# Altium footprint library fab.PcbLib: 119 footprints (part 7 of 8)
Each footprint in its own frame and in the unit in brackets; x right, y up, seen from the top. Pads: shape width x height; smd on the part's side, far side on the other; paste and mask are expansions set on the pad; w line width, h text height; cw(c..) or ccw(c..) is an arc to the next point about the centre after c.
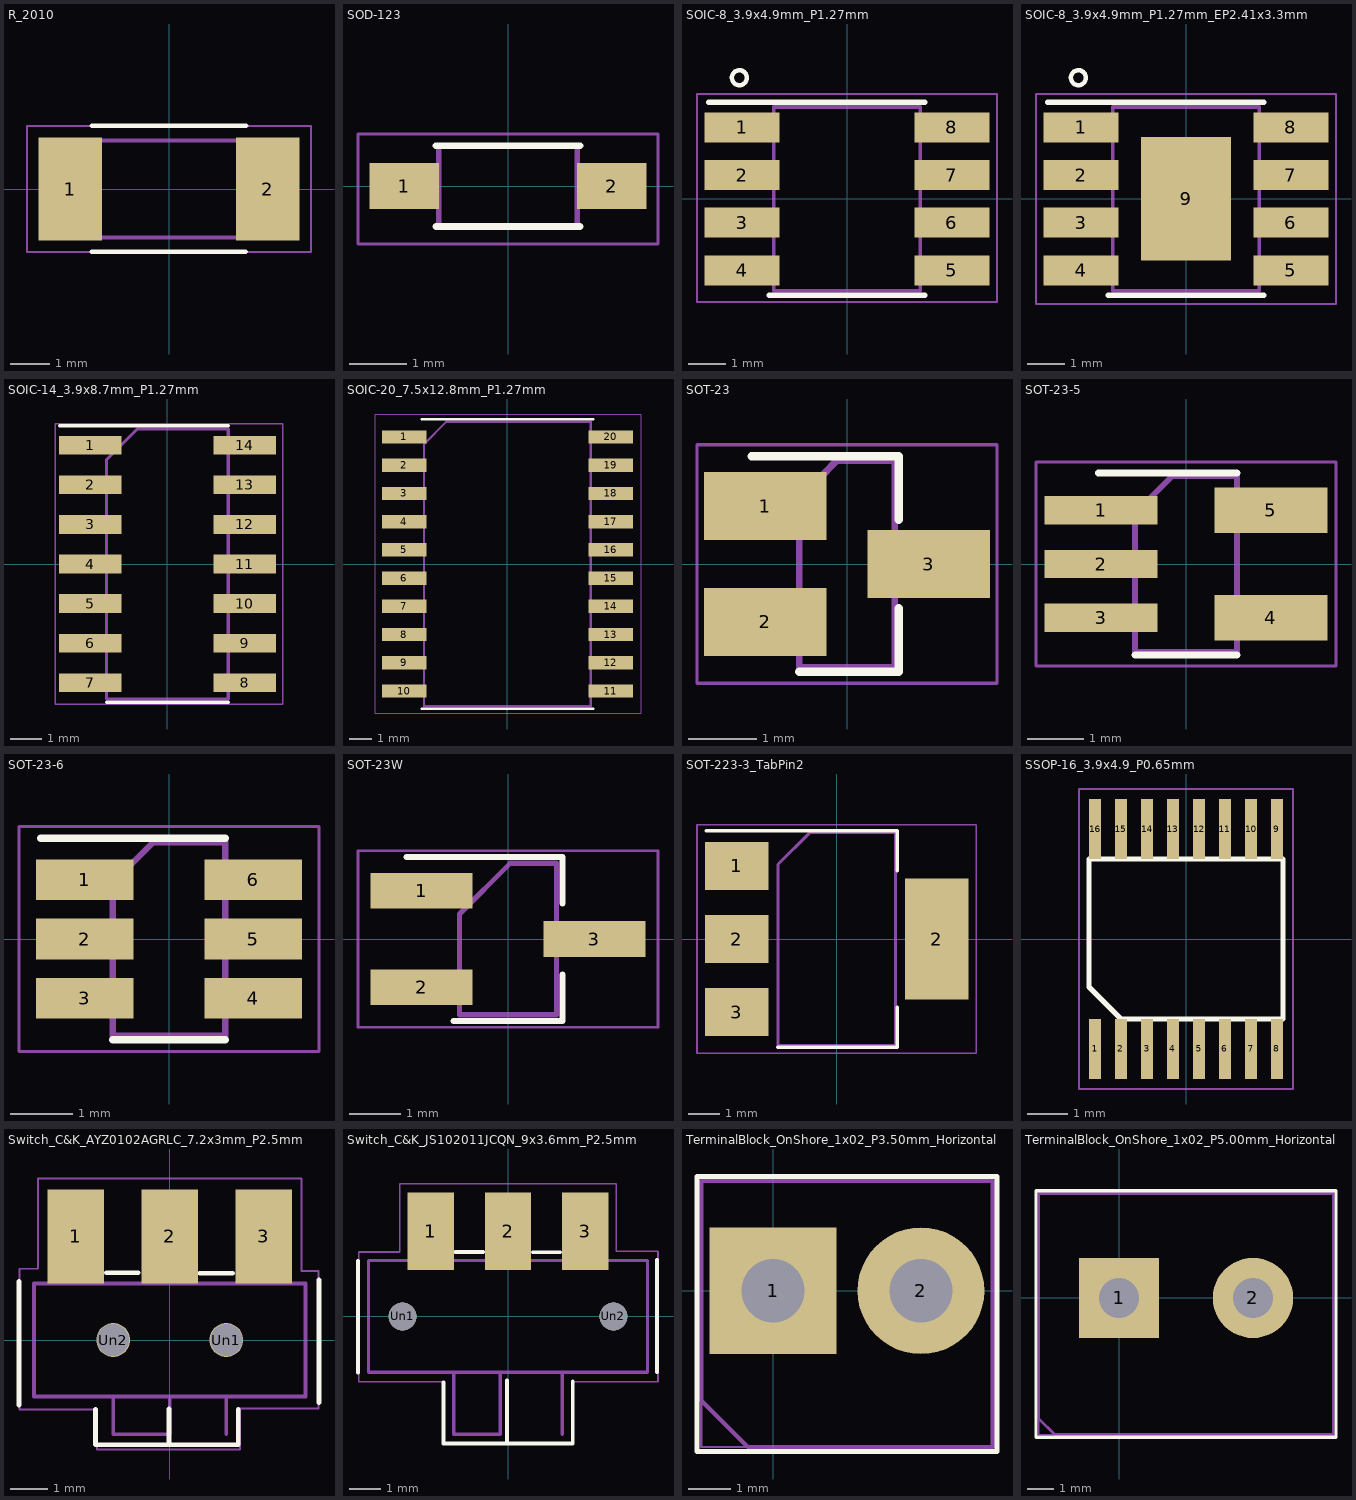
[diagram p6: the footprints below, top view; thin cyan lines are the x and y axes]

## R_2010 [mm]
pads (2):
  rect 1.6x2.6 smd: 1(-2.5,0) 2(2.5,0)
F.SilkS:
  lines w0.12: -1.96,-1.59 1.94,-1.59 ; -1.95,1.6 1.95,1.6
F.CrtYd:
  lines w0.05: -3.6,-1.6 3.6,-1.6 3.6,1.6 -3.6,1.6 -3.6,-1.6
F.Fab:
  lines w0.1: -2.5,-1.225 2.5,-1.225 2.5,1.225 -2.5,1.225 -2.5,-1.225
  text "%R" at -0.393,-0.294 h1

## SOD-123 [mm]
pads (2):
  rect 1.2x0.8 smd: 1(-1.8,0) 2(1.8,0)
F.SilkS:
  lines w0.12: -1.25,-0.7 1.25,-0.7 ; -1.25,0.7 1.25,0.7
B.CrtYd:
  lines w0.05: -2.6,-1 2.6,-1 2.6,0.9 -2.6,0.9 -2.6,-1
F.Fab:
  lines w0.1: -1.2,-0.7 1.2,-0.7 1.2,0.7 -1.2,0.7 -1.2,-0.7

## SOIC-8_3.9x4.9mm_P1.27mm [mm]
pads (8):
  rect 2x0.8 smd: 1(-2.8,1.905) 2(-2.8,0.635) 3(-2.8,-0.635) 4(-2.8,-1.905) 5(2.8,-1.905) 6(2.8,-0.635) 7(2.8,0.635) 8(2.8,1.905)
F.SilkS:
  circle w0.12: c-2.87,3.23 r0.2
  lines w0.15: -3.69,2.575 2.075,2.575 ; -2.075,-2.575 2.075,-2.575
B.CrtYd:
  lines w0.05: -4,-2.75 4,-2.75 4,2.8 -4,2.8 -4,-2.75
F.Fab:
  lines w0.1: -1.95,-2.45 1.95,-2.45 1.95,2.45 -1.95,2.45 -1.95,-2.45
  text "%R" at -0.353,-0.264 h0.9

## SOIC-8_3.9x4.9mm_P1.27mm_EP2.41x3.3mm [mm]
pads (9):
  rect 2x0.8 smd: 1(-2.8,1.905) 2(-2.8,0.635) 3(-2.8,-0.635) 4(-2.8,-1.905) 5(2.8,-1.905) 6(2.8,-0.635) 7(2.8,0.635) 8(2.8,1.905)
  rect 2.41x3.3 smd: 9(0,0)
F.SilkS:
  circle w0.12: c-2.87,3.23 r0.2
  lines w0.15: -3.69,2.575 2.075,2.575 ; -2.075,-2.575 2.075,-2.575
B.CrtYd:
  lines w0.05: -4,-2.8 -4,2.8 4,2.8 4,-2.8 -4,-2.8
F.Fab:
  lines w0.1: -1.95,-2.45 -1.95,2.45 1.95,2.45 1.95,-2.45 -1.95,-2.45
  text "%R" at -0.353,-0.264 h0.9

## SOIC-14_3.9x8.7mm_P1.27mm [mm]
pads (14):
  rect 2x0.6 smd: 1(-2.475,3.81) 2(-2.475,2.54) 3(-2.475,1.27) 4(-2.475,0) 5(-2.475,-1.27) 6(-2.475,-2.54) 7(-2.475,-3.81) 8(2.475,-3.81) 9(2.475,-2.54) 10(2.475,-1.27) 11(2.475,0) 12(2.475,1.27) 13(2.475,2.54) 14(2.475,3.81)
F.SilkS:
  lines w0.12: -3.45,4.435 0,4.435 1.95,4.435 ; -1.95,-4.435 0,-4.435 1.95,-4.435
F.CrtYd:
  lines w0.05: -3.6,-4.5 3.7,-4.5 3.7,4.5 -3.6,4.5 -3.6,-4.5
  text "%R" at -0.393,-0.294 h1
F.Fab:
  lines w0.1: -1.95,-4.325 -1.95,3.35 -0.975,4.325 1.95,4.325 1.95,-4.325 -1.95,-4.325

## SOIC-20_7.5x12.8mm_P1.27mm [mm]
pads (20):
  rect 2x0.6 smd: 1(-4.65,5.715) 2(-4.65,4.445) 3(-4.65,3.175) 4(-4.65,1.905) 5(-4.65,0.635) 6(-4.65,-0.635) 7(-4.65,-1.905) 8(-4.65,-3.175) 9(-4.65,-4.445) 10(-4.65,-5.715) 11(4.65,-5.715) 12(4.65,-4.445) 13(4.65,-3.175) 14(4.65,-1.905) 15(4.65,-0.635) 16(4.65,0.635) 17(4.65,1.905) 18(4.65,3.175) 19(4.65,4.445) 20(4.65,5.715)
F.SilkS:
  lines w0.12: -3.86,-6.51 0,-6.51 3.86,-6.51 ; -3.86,6.51 0,6.51 3.86,6.51
B.CrtYd:
  lines w0.05: -5.95,-6.75 -5.95,6.75 6,6.75 6,-6.75 -5.95,-6.75
  text "%R" at -0.393,-0.294 h1
F.Fab:
  lines w0.1: -3.75,-6.4 3.75,-6.4 3.75,6.4 -2.75,6.4 -3.75,5.4 -3.75,-6.4

## SOT-23 [mm]
pads (3):
  rect 1.8x1 smd: 1(-1.2,0.85) 2(-1.2,-0.85) 3(1.2,0)
F.SilkS:
  lines w0.12: -1.4,1.58 0.76,1.58 0.76,0.65 ; -0.7,-1.58 0.76,-1.58 0.76,-0.65
F.CrtYd:
  lines w0.05: -2.2,-1.75 2.2,-1.75 2.2,1.75 -2.2,1.75 -2.2,-1.75
F.Fab:
  lines w0.1: -0.7,-1.52 0.7,-1.52 0.7,1.52 -0.15,1.52 -0.7,0.95 -0.7,-1.5
  text "%R" at 0.147,-0.197 h0.5

## SOT-23-5 [mm]
pads (5):
  rect 2x0.5 smd: 1(-1.5,0.95) 2(-1.5,0) 3(-1.5,-0.95)
  rect 2x0.8 smd: 4(1.5,-0.95) 5(1.5,0.95)
F.SilkS:
  lines w0.12: -1.55,1.61 0.9,1.61 ; -0.9,-1.61 0.9,-1.61
F.CrtYd:
  lines w0.05: -2.65,-1.8 -2.65,1.8 2.65,1.8 2.65,-1.8 -2.65,-1.8
F.Fab:
  lines w0.1: -0.9,-1.55 -0.9,0.9 -0.25,1.55 0.9,1.55 0.9,-1.55 -0.9,-1.55
  text "%R" at 0.147,-0.197 h0.5

## SOT-23-6 [mm]
pads (6):
  rect 1.56x0.65 smd: 1(-1.35,0.95) 2(-1.35,0) 3(-1.35,-0.95) 4(1.35,-0.95) 5(1.35,0) 6(1.35,0.95)
F.SilkS:
  lines w0.12: -2.05,1.61 0.9,1.61 ; -0.9,-1.61 0.9,-1.61
F.CrtYd:
  lines w0.05: -2.4,-1.8 2.4,-1.8 2.4,1.8 -2.4,1.8 -2.4,-1.8
F.Fab:
  lines w0.1: -0.9,-1.55 0.9,-1.55 0.9,1.55 -0.25,1.55 -0.9,0.9 -0.9,-1.55
  text "%R" at 0.147,-0.197 h0.5

## SOT-23W [mm]
pads (3):
  rect 2x0.7 smd: 1(-1.7,0.95) 2(-1.7,-0.95) 3(1.7,0)
F.SilkS:
  lines w0.12: -2,1.61 1.075,1.61 ; -1.075,-1.61 1.075,-1.61 1.075,-0.7 ; 1.075,0.7 1.075,1.6
F.CrtYd:
  lines w0.05: -2.95,-1.74 2.95,-1.74 2.95,1.74 -2.95,1.74 -2.95,-1.74
F.Fab:
  lines w0.1: -0.955,-1.49 -0.955,0.49 0.045,1.49 0.955,1.49 0.955,-1.49 -0.955,-1.49
  text "%R" at 0.147,-0.197 h0.5

## SOT-223-3_TabPin2 [mm]
pads (4):
  rect 2x1.5 smd: 1(-3.15,2.3) 2(-3.15,0) 3(-3.15,-2.3)
  rect 2x3.8 smd: 2(3.15,0)
F.SilkS:
  lines w0.12: -4.1,3.41 1.91,3.41 1.91,2.15 ; -1.85,-3.41 1.91,-3.41 1.91,-2.15
F.CrtYd:
  lines w0.05: -4.4,-3.6 4.4,-3.6 4.4,3.6 -4.4,3.6 -4.4,-3.6
F.Fab:
  lines w0.1: -1.85,-3.35 -1.85,2.35 -0.85,3.35 1.85,3.35 1.85,-3.35 -1.85,-3.35
  text "%R" at 0.234,-0.313 h0.8

## SSOP-16_3.9x4.9_P0.65mm [mm]
pads (16):
  rect 0.3x1.5 smd: 1(-2.275,-2.75) 2(-1.625,-2.75) 3(-0.975,-2.75) 4(-0.325,-2.75) 5(0.325,-2.75) 6(0.975,-2.75) 7(1.625,-2.75) 8(2.275,-2.75) 9(2.275,2.75) 10(1.625,2.75) 11(0.975,2.75) 12(0.325,2.75) 13(-0.325,2.75) 14(-0.975,2.75) 15(-1.625,2.75) 16(-2.275,2.75)
F.SilkS:
  lines w0.12: -2.425,-1.2 -1.625,-2 2.425,-2 2.425,2 -2.425,2 -2.425,-1.2
F.CrtYd:
  lines w0.05: -2.68,-3.75 2.68,-3.75 2.68,3.75 -2.68,3.75 -2.68,-3.75

## Switch_C&K_AYZ0102AGRLC_7.2x3mm_P2.5mm [mm]
pads (5):
  rect 1.5x2.5 smd: 1(-2.5,2.75) 2(0,2.75) 3(2.5,2.75)
  round 0.9 hole 0.85: Un1(1.5,0) Un2(-1.5,0)
F.SilkS:
  lines w0.12: -4,-1.73 -4,1.56 ; -1.97,-1.84 -1.97,-2.78 1.82,-2.78 1.82,-1.84 ; -1.68,1.78 -0.83,1.78 ; -0.02,-2.77 -0.02,-1.82 ; 0.8,1.77 1.67,1.77 ; 3.96,-1.67 3.96,1.6
F.CrtYd:
  lines w0.05: -3.99,-1.84 -1.93,-1.84 -1.93,-2.91 1.86,-2.91 1.86,-1.82 3.95,-1.82 3.95,1.83 3.5,1.83 3.5,4.29 -3.5,4.29 -3.5,1.89 -3.99,1.89 -3.99,-1.84
F.Fab:
  lines w0.1: -1.5,-1.5 -1.5,-2.5 0,-2.5 0,-1.5 ; 1.5,-2.5 1.5,-1.5 ; -3.6,-1.5 -3.6,1.5 3.6,1.5 3.6,-1.5 -3.6,-1.5
  text "%R" at -0.393,-0.294 h1

## Switch_C&K_JS102011JCQN_9x3.6mm_P2.5mm [mm]
pads (5):
  rect 1.5x2.5 smd: 1(-2.5,2.75) 2(0,2.75) 3(2.5,2.75)
  round 0.9 hole 0.9: Un1(-3.4,0) Un2(3.4,0)
F.SilkS:
  lines w0.12: -4.84,-1.81 -4.84,1.8 ; -2.08,-2.12 -2.08,-4.1 2.09,-4.1 2.09,-2.09 ; -1.7,2.08 -0.81,2.08 ; -0.03,-4.09 -0.03,-2.06 ; 0.8,2.07 1.69,2.07 ; 4.81,-1.8 4.81,1.83
F.CrtYd:
  lines w0.05: -4.81,-2.11 -4.81,2.08 -3.5,2.08 -3.5,4.29 3.5,4.29 3.5,2.1 4.84,2.1 4.84,-2.11 2.08,-2.11 2.08,-4.13 -2.07,-4.13 -2.07,-2.11 -4.81,-2.11
F.Fab:
  lines w0.1: -1.75,-1.8 -1.75,-3.8 -0.25,-3.8 -0.25,-1.8 ; 1.75,-3.8 1.75,-1.8 ; -4.5,-1.8 4.5,-1.8 4.5,1.8 -4.5,1.8 -4.5,-1.8
  text "%R" at -0.393,-0.294 h1

## TerminalBlock_OnShore_1x02_P3.50mm_Horizontal [mm]
pads (2):
  rect 3x3 hole 1.5: 1(0,0)
  round 3 hole 1.5: 2(3.5,0)
F.SilkS:
  lines w0.12: -1.8,-3.8 -1.8,2.7 5.3,2.7 5.3,-3.8 -1.8,-3.8
F.CrtYd:
  lines w0.05: -1.7,-3.7 5.2,-3.7 5.2,2.6 -1.7,2.6 -1.7,-3.7
F.Fab:
  lines w0.1: -1.7,-2.6 -1.7,2.6 5.2,2.6 5.2,-3.7 -0.6,-3.7 -1.7,-2.6
  text "%R" at 1.357,-3.194 h1

## TerminalBlock_OnShore_1x02_P5.00mm_Horizontal [mm]
pads (2):
  rect 3x3 hole 1.5: 1(0,0)
  round 3 hole 1.5: 2(5,0)
F.SilkS:
  lines w0.12: -3.1,-5.2 -3.1,4 8.1,4 8.1,-5.2 -3.1,-5.2
F.CrtYd:
  lines w0.05: -3,-5.1 8,-5.1 8,3.9 -3,3.9 -3,-5.1
F.Fab:
  lines w0.1: -3,-4.5 -3,3.9 8,3.9 8,-5.1 -2.4,-5.1 -3,-4.5
  text "%R" at 2.107,-3.094 h1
